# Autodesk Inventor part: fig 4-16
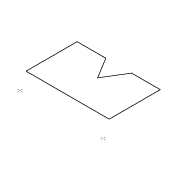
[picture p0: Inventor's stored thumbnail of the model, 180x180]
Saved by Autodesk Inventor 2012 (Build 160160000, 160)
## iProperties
Created: 2005-02
Part Number: fig 4-16
Document SubType Name: Modeling
Designer: CADCIM
Manufacturer: Standard
Standards Organization: Custom
Density: 1 g/cm^3
Material: Default
Author: CADCIM
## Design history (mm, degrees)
sketch "Sketch1"
  geometry: L1 (-25.19, 27.524)-(-25.19, 5.557); L2 (-25.19, 5.557)-(10.567, 5.557); L3 (10.567, 5.557)-(10.567, 27.524); L4 (10.567, 27.524)-(-1.76, 27.524); L5 (-1.76, 27.524)-(-7.312, 18.449); L6 (-7.312, 18.449)-(-12.863, 27.524); L7 (-12.863, 27.524)-(-25.19, 27.524); 2 further points
  constraints: 14 end point, 3 equal length, 3 parallel, 1 perpendicular, 1 vertical, 1 other
